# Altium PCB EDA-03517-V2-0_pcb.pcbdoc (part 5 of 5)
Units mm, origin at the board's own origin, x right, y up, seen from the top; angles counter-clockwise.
Board outline 220 x 264 mm, 8 copper layers (Top Layer, L2, L3, L4, L5, L6, L7, Bottom Layer), stack 2.18 mm thick; 439 components, 290 nets, 1011 pads, 273 vias.
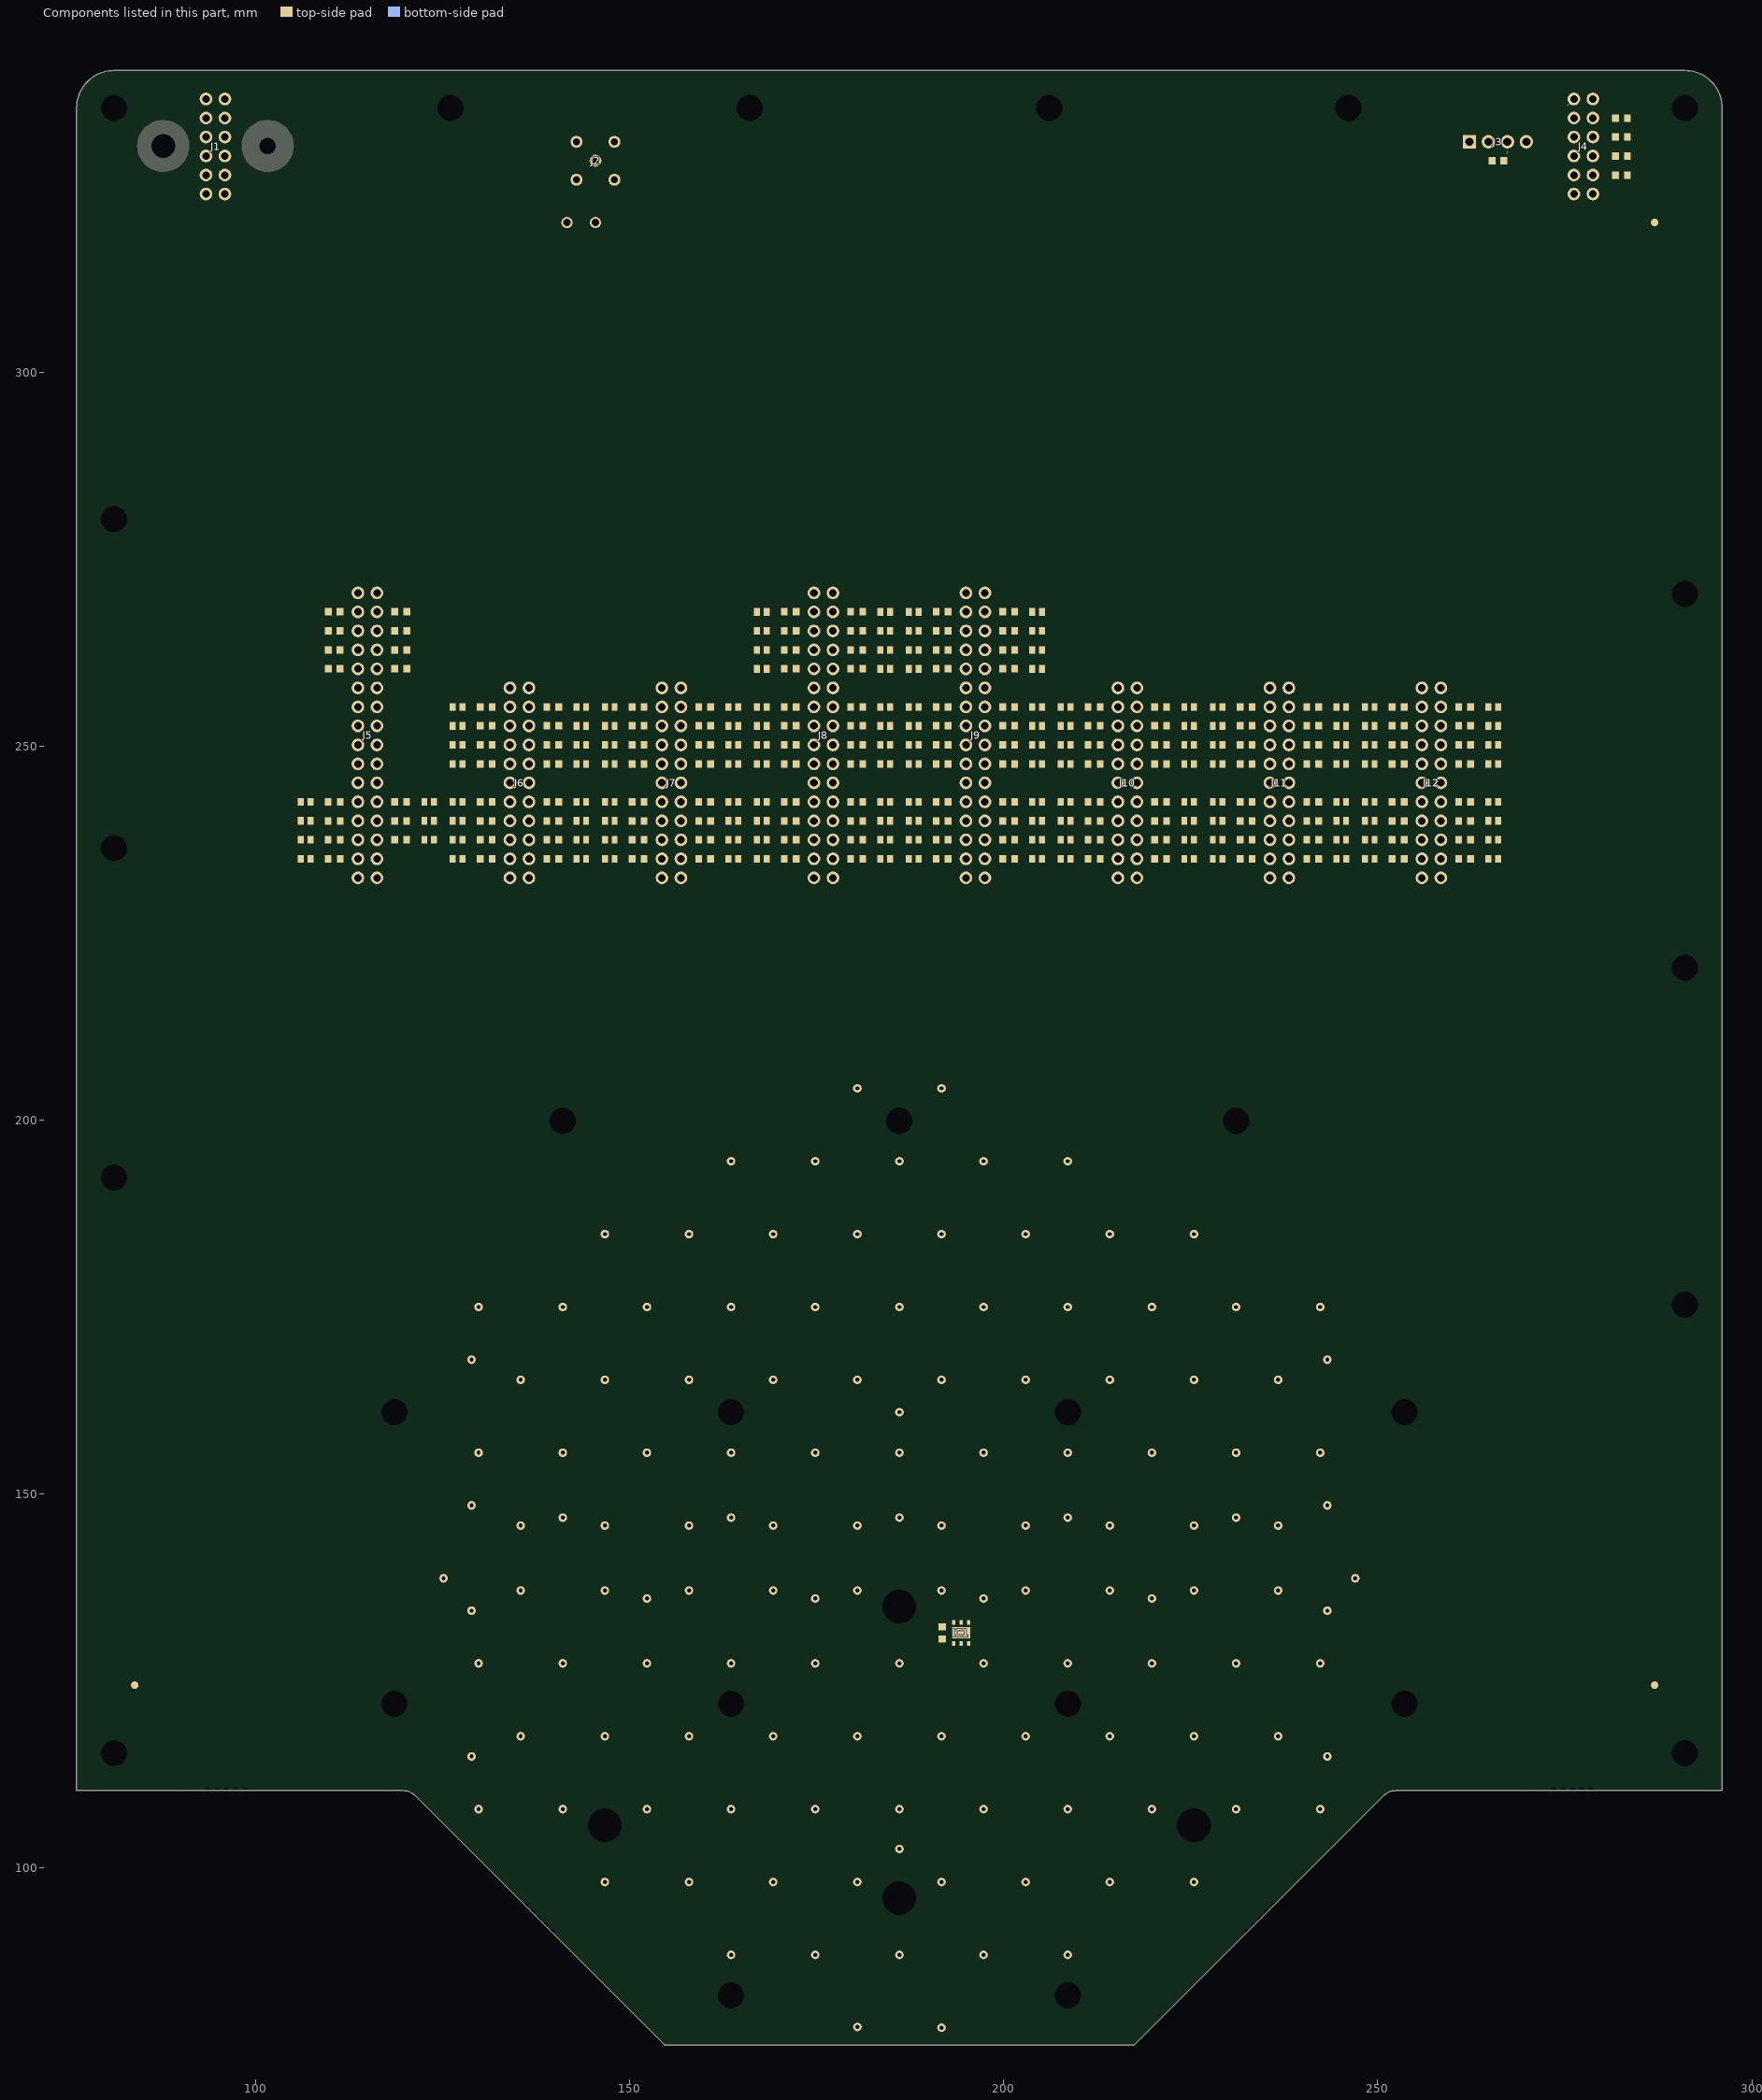
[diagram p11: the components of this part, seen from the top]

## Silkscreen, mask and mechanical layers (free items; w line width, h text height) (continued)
Mechanical 1:
  lines w0.8: 99.055,107.96 cw(c99.055,109.16) 99.055,110.36 119.661,110.36 ; 99.06,107.96 119.661,107.96 133.988,93.633 ccw(c134.837,94.481) 135.685,95.33 121.358,109.657 ; 119.671,110.37 cw(c119.671,107.97) 121.368,109.667 ; 250.752,109.657 236.434,95.339 ccw(c237.282,94.49) 238.131,93.641 252.449,107.96 273.055,107.96 ccw(c273.055,109.16) 273.055,110.36 252.449,110.36 ; 250.762,109.667 cw(c252.459,107.97) 252.459,110.37 ; 76.055,76.36 151.261,76.36 138.231,89.39 cw(c139.079,90.239) 139.928,91.087 154.655,76.36 217.455,76.36 232.191,91.096 cw(c233.039,90.247) 233.888,89.399 220.849,76.36 296.055,76.36 296.055,107.96 279.055,107.96 cw(c279.055,109.16) 279.055,110.36 296.055,110.36 296.055,335.36 ccw(c291.055,335.36) 291.055,340.36 81.055,340.36 ccw(c81.055,335.36) 76.055,335.36 76.055,110.36 93.055,110.36 cw(c93.055,109.16) 93.055,107.96 76.055,107.96 76.055,76.36
Mechanical 2:
  text "Components" at 200.66,45.72 h1.91
  text ".Component_Count" at 218.44,45.72 h1.91
  text "Pins" at 200.66,43.18 h1.91
  text ".Pad_Count" at 218.44,43.18 h1.91
  text "Vias" at 200.66,40.64 h1.91
  text ".Via_Count" at 218.44,40.64 h1.91
  text "Holes" at 200.66,38.1 h1.91
  text ".Hole_Count" at 218.44,38.1 h1.91
  text "Nets" at 200.66,35.56 h1.91
  text ".Net_Count" at 218.44,35.56 h1.91
Mechanical 3:
  drawing of 3981 lines, arcs and shapes, not listed
  text "1" at 180.041,205.031 h1
  text "2" at 191.293,205.031 h1
  text "3" at 163.163,195.286 h1
  text "4" at 174.415,195.286 h1
  text "5" at 185.667,195.286 h1
  text "6" at 196.919,195.286 h1
  text "7" at 208.171,195.286 h1
  text "8" at 146.285,185.542 h1
  text "9" at 157.537,185.542 h1
  text "10" at 168.4,185.542 h1
  text "11" at 179.652,185.542 h1
  text "12" at 190.904,185.542 h1
  text "13" at 202.156,185.542 h1
  text "14" at 213.408,185.542 h1
  text "15" at 224.66,185.542 h1
  text "16" at 129.018,175.797 h1
  text "17" at 140.27,175.797 h1
  text "18" at 151.522,175.797 h1
  text "19" at 162.774,175.797 h1
  text "20" at 174.026,175.797 h1
  text "21" at 185.278,175.797 h1
  text "22" at 196.53,175.797 h1
  text "23" at 207.782,175.797 h1
  text "24" at 219.034,175.797 h1
  text "25" at 230.286,175.797 h1
  text "26" at 241.538,175.797 h1
  text "27" at 128.075,168.756 h1
  text "38" at 242.481,168.756 h1
  text "28" at 134.644,166.053 h1
  text "29" at 145.896,166.053 h1
  text "30" at 157.148,166.053 h1
  text "31" at 168.4,166.053 h1
  text "32" at 179.652,166.053 h1
  text "33" at 190.904,166.053 h1
  text "34" at 202.156,166.053 h1
  text "35" at 213.408,166.053 h1
  text "36" at 224.66,166.053 h1
  text "37" at 235.912,166.053 h1
  text "39" at 185.278,161.715 h1
  text "40" at 129.018,156.308 h1
  text "41" at 140.27,156.308 h1
  text "42" at 151.522,156.308 h1
  text "43" at 162.774,156.308 h1
  text "44" at 174.026,156.308 h1
  text "45" at 185.278,156.308 h1
  text "46" at 196.53,156.308 h1
  text "47" at 207.782,156.308 h1
  text "48" at 219.034,156.308 h1
  text "49" at 230.286,156.308 h1
  text "50" at 241.538,156.308 h1
  text "51" at 128.075,149.267 h1
  text "62" at 242.481,149.267 h1
  text "64" at 140.27,147.634 h1
  text "66" at 162.774,147.634 h1
  text "68" at 185.278,147.634 h1
  text "70" at 207.782,147.634 h1
  text "72" at 230.286,147.634 h1
  text "52" at 134.644,146.564 h1
  text "53" at 145.896,146.564 h1
  text "54" at 157.148,146.564 h1
  text "55" at 168.4,146.564 h1
  text "56" at 179.652,146.564 h1
  text "57" at 190.904,146.564 h1
  text "58" at 202.156,146.564 h1
  text "59" at 213.408,146.564 h1
  text "60" at 224.66,146.564 h1
  text "61" at 235.912,146.564 h1
  text "63" at 124.335,139.523 h1
  text "73" at 246.221,139.523 h1
  text "75" at 134.644,137.889 h1
  text "76" at 145.896,137.889 h1
  text "77" at 157.148,137.889 h1
  text "78" at 168.4,137.889 h1
  text "79" at 179.652,137.889 h1
  text "80" at 190.904,137.889 h1
  text "81" at 202.156,137.889 h1
  text "82" at 213.408,137.889 h1
  text "83" at 224.66,137.889 h1
  text "84" at 235.912,137.889 h1
  text "65" at 151.522,136.819 h1
  text "67" at 174.026,136.819 h1
  text "69" at 196.53,136.819 h1
  text "71" at 219.034,136.819 h1
  text "1" at 185.667,135.73 h1
  text "74" at 128.075,135.185 h1
  text "85" at 242.481,135.185 h1
  text "86" at 129.018,128.145 h1
  text "87" at 140.27,128.145 h1
  text "88" at 151.522,128.145 h1
  text "89" at 162.774,128.145 h1
  text "90" at 174.026,128.145 h1
  text "91" at 185.278,128.145 h1
  text "92" at 196.53,128.145 h1
  text "93" at 207.782,128.145 h1
  text "94" at 219.034,128.145 h1
  text "95" at 230.286,128.145 h1
  text "96" at 241.538,128.145 h1
  text "98" at 134.644,118.4 h1
  text "99" at 145.896,118.4 h1
  text "100" at 156.76,118.4 h1
  text "101" at 168.012,118.4 h1
  text "102" at 179.264,118.4 h1
  text "103" at 190.516,118.4 h1
  text "104" at 201.768,118.4 h1
  text "105" at 213.02,118.4 h1
  text "106" at 224.272,118.4 h1
  text "107" at 235.524,118.4 h1
  text "97" at 128.075,115.696 h1
  text "108" at 242.093,115.696 h1
  text "109" at 128.63,108.656 h1
  text "110" at 139.882,108.656 h1
  text "111" at 151.134,108.656 h1
  text "112" at 162.386,108.656 h1
  text "113" at 173.638,108.656 h1
  text "114" at 184.89,108.656 h1
  text "115" at 196.142,108.656 h1
  text "116" at 207.394,108.656 h1
  text "117" at 218.646,108.656 h1
  text "118" at 229.898,108.656 h1
  text "119" at 241.15,108.656 h1
  text "4" at 146.285,106.496 h1
  text "3" at 225.049,106.496 h1
  text "120" at 184.89,103.248 h1
  text "121" at 145.508,98.911 h1
  text "122" at 156.76,98.911 h1
  text "123" at 168.012,98.911 h1
  text "124" at 179.264,98.911 h1
  text "125" at 190.516,98.911 h1
  text "126" at 201.768,98.911 h1
  text "127" at 213.02,98.911 h1
  text "128" at 224.272,98.911 h1
  text "2" at 185.667,96.752 h1
  text "129" at 162.386,89.167 h1
  text "130" at 173.638,89.167 h1
  text "131" at 184.89,89.167 h1
  text "132" at 196.142,89.167 h1
  text "133" at 207.394,89.167 h1
  text "134" at 179.264,79.422 h1
  text "135" at 190.516,79.422 h1
Mechanical 4:
  drawing of 882 lines, arcs and shapes, not listed
Corners:
  lines w0.2: 71.055,76.36 76.055,76.36 76.055,71.36 ; 71.055,340.36 81.055,340.36 ; 76.055,335.36 76.055,345.36 ; 291.055,340.36 301.055,340.36 ; 296.055,71.36 296.055,76.36 301.055,76.36 ; 296.055,335.36 296.055,345.36
  lines w0.254: 146.05,35.56 146.05,40.64 ; 151.13,35.56 151.13,40.64 ; 156.21,35.56 156.21,40.64 ; 161.29,35.56 161.29,40.64 ; 166.37,35.56 166.37,40.64 ; 171.45,35.56 171.45,40.64 ; 176.53,35.56 176.53,40.64 ; 140.97,35.56 140.97,40.64 181.61,40.64 181.61,35.56 140.97,35.56
Title Block:
  circle w0.305: c80.645,48.26 r3.81
  lines w0.254: 78.74,46.998 ccw(c83.185,46.99) 79.453,49.404 ; 87.63,46.99 87.63,51.435 ; 90.17,43.815 132.08,43.815 ; 90.17,46.99 132.08,46.99 ; 90.17,50.165 132.08,50.165 ; 104.14,40.64 104.14,53.34 ; 76.2,40.64 76.2,53.34 88.9,53.34 88.9,40.64 76.2,40.64 ; 90.17,40.64 90.17,53.34 132.08,53.34 132.08,40.64 90.17,40.64
  lines w0.305: 77.089,46.888 78.105,43.815 ; 80.137,40.767 83.21,45.441 ; 80.645,52.07 88.265,52.705 ; 84.379,49.022 86.995,40.64
  text "Number" at 91.44,50.8 h1.91
  text "EDA-03517-V2" at 105.41,50.8 h1.91
  text "Drawn By" at 91.44,47.625 h1.91
  text "JMW" at 105.41,47.625 h1.91
  text "CERN" at 77.47,47.371 h2.54
  text "DATE" at 91.44,44.45 h1.91
  text "10-11-2016" at 105.41,44.45 h1.91
  text "MOD.V2" at 91.44,41.275 h1.91
  text "JMW 08-02-2019" at 105.41,41.275 h1.91
  text "Print Date" at 91.44,38.1 h1.27
  text ".Print_Date" at 106.68,38.1 h1.27
  text ".Print_Time" at 119.38,38.1 h1.27
  text ".Print_Scale" at 91.44,35.56 h1.27
Notvisible:
  drawing of 177 lines, arcs and shapes, not listed
  text "TE/MPE" at 187.007,314.96 h1
  text "CERN" at 178.308,312.801 h1.25
  text "SK/JMW" at 186.69,309.245 h1
  text "Misc1 glued  (ISOTAC) on Bottom Side" at 116.84,213.36 h1.5
  text "see Detail" at 116.84,210.82 h1.5
  text "Assembly Detail with EDA-03517-Vx-0_misc1" at 251.46,54.61 h1.5
  text "D3.5mm" at 260.35,49.53 h1.5
  text "D0.5mm" at 283.845,49.53 h1.5
  text "Top" at 241.3,47.625 h1
  text "PCB" at 300.99,45.72 h1.5
  text "2.2mm" at 247.015,45.402 h1.5
  text "Bot" at 241.3,44.45 h1
  text "Laminating Adhesive" at 300.99,42.545 h1.5
  text "Top" at 241.3,40.005 h1
  text "(ISOTAC or eq.)" at 307.34,40.005 h1.5
  text "2.4mm" at 247.015,38.735 h1.5
  text "Misc1" at 300.99,37.465 h1.5
  text "Bot" at 241.3,36.83 h1
  text "D1.2mm" at 283.845,33.655 h1.5
  text "0.05" at 273.368,32.861 h1.5
  text "(Not to Scale)" at 241.3,31.75 h1
  text "Holes must be concentric to +/-0.05mm" at 272.415,29.21 h1.5
Panelisation:
  lines w0.2: 76.055,92.36 136.958,92.36 136.958,76.36 ; 96.055,107.96 96.055,110.36 ; 136.109,91.511 137.806,93.209 ; 234.312,93.217 236.009,91.52 ; 235.152,76.36 235.152,92.36 ; 276.055,107.96 276.055,110.36
  text "Not Plated Holes" at 99.695,115.57 h1
Panelisation2:
  lines w2.4: 76.055,109.16 93.055,109.16 ; 99.055,109.16 119.661,109.16 cw(c119.661,107.96) 120.509,108.809 134.837,94.481 ; 139.079,90.239 152.958,76.36 ; 219.152,76.36 233.039,90.247 ; 237.282,94.49 251.601,108.809 cw(c252.449,107.96) 252.449,109.16 273.055,109.16 ; 279.055,109.16 296.055,109.16
Drill Drawing:
  circle w0.25: c170.218,310.398 r0.833
  lines w0.25: 169.385,287.065 169.385,287.482 169.801,287.898 169.385,288.315 169.385,288.732 169.801,288.732 170.218,288.315 170.635,288.732 171.051,288.732 171.051,288.315 170.635,287.898 171.051,287.482 171.051,287.065 170.635,287.065 170.218,287.482 169.801,287.065 169.385,287.065 ; 169.385,290.815 171.051,290.815 171.051,292.482 169.385,292.482 169.385,290.815 ; 169.385,295.398 170.218,294.565 171.051,295.398 170.218,296.232 169.385,295.398 ; 169.385,299.982 171.051,299.982 170.218,298.315 169.385,299.982 ; 169.385,302.065 170.218,302.482 171.051,302.065 170.635,302.898 171.051,303.732 170.218,303.315 169.385,303.732 169.801,302.898 169.385,302.065 ; 169.385,306.232 169.801,306.232 169.801,305.815 170.635,305.815 170.635,306.232 171.051,306.232 171.051,307.065 170.635,307.065 170.635,307.482 169.801,307.482 169.801,307.065 169.385,307.065 169.385,306.232 ; 169.385,314.982 171.051,314.982 170.218,313.315 169.385,314.982 ; 169.385,317.065 170.218,317.482 171.051,317.065 170.635,317.898 171.051,318.732 170.218,318.315 169.385,318.732 169.801,317.898 169.385,317.065 ; 169.385,321.232 169.801,321.232 170.218,320.815 170.635,321.232 171.051,321.232 170.635,321.648 171.051,322.065 170.635,322.065 170.218,322.482 169.801,322.065 169.385,322.065 169.801,321.648 169.385,321.232 ; 169.718,299.648 170.718,299.648 170.218,298.648 169.718,299.648 ; 169.718,302.398 170.218,302.648 170.718,302.398 170.468,302.898 170.718,303.398 170.218,303.148 169.718,303.398 169.968,302.898 169.718,302.398
  lines w0.5: 167.89,285.94 261.024,285.94 ; 167.89,323.44 261.024,323.44 ; 180.455,282.19 180.455,327.19 ; 195.031,282.19 195.031,327.19 ; 220.225,282.19 220.225,327.19 ; 230.147,282.19 230.147,327.19 ; 242.427,282.19 242.427,327.19 ; 167.89,282.19 261.024,282.19 261.024,327.19 167.89,327.19 167.89,282.19
  text "Symbol" at 170.14,324.565 h1.8
  text "Hit Count" at 181.58,324.565 h1.8
  text "Finished Hole Size" at 196.156,324.565 h1.8
  text "Plated" at 221.35,324.565 h1.8
  text "Via/Pad" at 231.272,324.565 h1.8
  text "New column" at 243.552,324.565 h1.8
  text "273" at 181.58,320.815 h1.5
  text "0.50mm (19.69mil)" at 196.156,320.815 h1.5
  text "PTH" at 221.35,320.815 h1.5
  text "Via" at 231.272,320.815 h1.5
  text "135" at 181.58,317.065 h1.5
  text "0.55mm (21.65mil)" at 196.156,317.065 h1.5
  text "PTH" at 221.35,317.065 h1.5
  text "Pad" at 231.272,317.065 h1.5
  text "5" at 181.58,313.315 h1.5
  text "0.90mm (35.43mil)" at 196.156,313.315 h1.5
  text "PTH" at 221.35,313.315 h1.5
  text "Pad" at 231.272,313.315 h1.5
  text "232" at 181.58,309.565 h1.5
  text "1.00mm (39.37mil)" at 196.156,309.565 h1.5
  text "PTH" at 221.35,309.565 h1.5
  text "Pad" at 231.272,309.565 h1.5
  text "4" at 181.58,305.815 h1.5
  text "1.10mm (43.31mil)" at 196.156,305.815 h1.5
  text "PTH" at 221.35,305.815 h1.5
  text "Pad" at 231.272,305.815 h1.5
  text "1" at 181.58,302.065 h1.5
  text "2.20mm (86.61mil)" at 196.156,302.065 h1.5
  text "PTH" at 221.35,302.065 h1.5
  text "Pad" at 231.272,302.065 h1.5
  text "1" at 181.58,298.315 h1.5
  text "3.20mm (125.98mil)" at 196.156,298.315 h1.5
  text "PTH" at 221.35,298.315 h1.5
  text "Pad" at 231.272,298.315 h1.5
  text "20" at 181.58,294.565 h1.5
  text "0.80mm (31.50mil)" at 196.156,294.565 h1.5
  text "NPTH" at 221.35,294.565 h1.5
  text "Pad" at 231.272,294.565 h1.5
  text "Panel Holes" at 243.552,294.565 h1.5
  text "27" at 181.58,290.815 h1.5
  text "3.50mm (137.80mil)" at 196.156,290.815 h1.5
  text "NPTH" at 221.35,290.815 h1.5
  text "Pad" at 231.272,290.815 h1.5
  text "4" at 181.58,287.065 h1.5
  text "4.50mm (177.17mil)" at 196.156,287.065 h1.5
  text "NPTH" at 221.35,287.065 h1.5
  text "Pad" at 231.272,287.065 h1.5
  text "702 Total" at 181.58,283.315 h1.5
  text "General tolerances +/-0.05mm unless otherwise stated" at 170.18,279.4 h1.5
  text "r=2.4mm" at 123.19,110.49 h1.5
  text "45deg" at 139.065,78.74 h1.5

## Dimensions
76.055,76.36 to 96.055,107.96 on Panelisation
81.055,340.36 to 81.055,335.36 on Drill Drawing
81.055,335.36 to 76.055,335.36 on Drill Drawing
97.305,110.36 to 100.701,113.756 on Panelisation
93.055,107.96 to 99.06,107.96 on Panelisation
94.805,110.36 to 93.555,110.36 on Panelisation
291.055,335.36 to 298.731,343.036 on Drill Drawing
296.055,76.36 to 291.055,340.36 on Mechanical 2
76.055,335.36 to 296.055,335.36 on Mechanical 2
76.055,76.36 to 76.055,107.96 on Panelisation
